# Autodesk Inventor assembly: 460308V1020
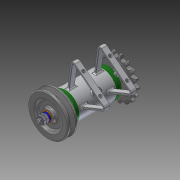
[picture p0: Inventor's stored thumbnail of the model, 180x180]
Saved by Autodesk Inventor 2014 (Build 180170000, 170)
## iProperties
Created: 2016-03
Part Number: 460308V1020
Document SubType Name: Assembly
Designer: 703-15
Author: 703-15
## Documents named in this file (16)
- C:\Users\703-15\Desktop\460308V1020\460308V1020.iam
- C:\Users\703-15\Desktop\460308V1020\460308V1020.ipt
- C:\Users\703-15\Desktop\460308V1020\커버.ipt
- C:\Users\703-15\Desktop\460308V1020\축.ipt
- C:\Users\703-15\Desktop\460308V1020\키 3 x 3 x 12.ipt
- C:\Users\703-15\Desktop\460308V1020\오일 실 15 25 7.ipt
- C:\Users\703-15\Desktop\460308V1020\베어링 15 x 32 x 9.ipt
- C:\Users\703-15\Desktop\460308V1020\볼트 M4 x 12.ipt
- C:\Users\703-15\Desktop\460308V1020\와셔 8x17.ipt
- C:\Users\703-15\Desktop\460308V1020\V벨트풀리.ipt
- C:\Users\703-15\Desktop\460308V1020\스프로킷.ipt
- C:\Users\703-15\Desktop\460308V1020\스프링와셔 8.ipt
- C:\Users\703-15\Desktop\460308V1020\니플 M 6 x 0.75.ipt
- C:\Users\703-15\Desktop\460308V1020\볼트 M 6 x 8.ipt
- C:\Users\703-15\Desktop\460308V1020\와셔 6x11.5.ipt
- C:\Users\703-15\Desktop\460308V1020\너트 M 8.ipt
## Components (12 placed, 4 different names)
1. KS B 2023 6002 - 15 x 32 x 9:1
2. KS B 2023 6002 - 15 x 32 x 9:2
3. V벨트풀리:1
4. 460308V1020:1
5. ISO 4762 M4 x 12:1
6. ISO 4762 M4 x 12:3
7. ISO 4762 M4 x 12:4
8. ISO 4762 M4 x 12:5
9. ISO 4762 M4 x 12:2
10. ISO 4762 M4 x 12:6
11. ISO 4762 M4 x 12:7
12. ISO 4762 M4 x 12:8
